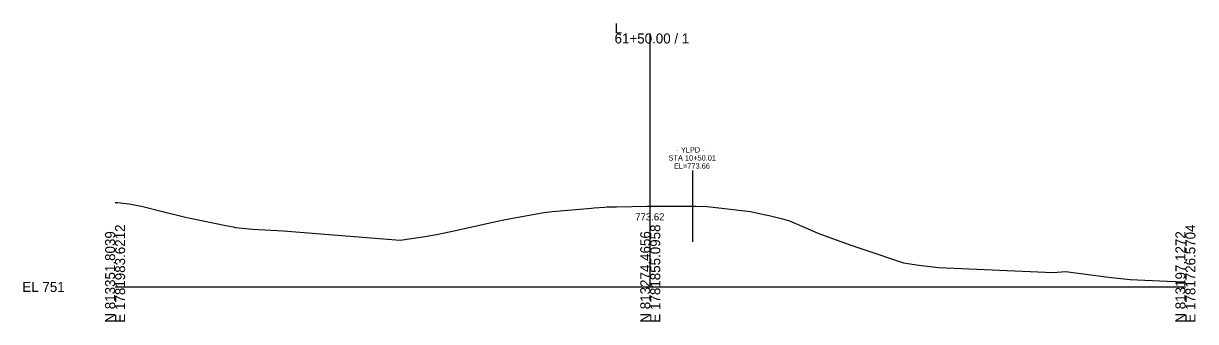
# Model space of a CAD drawing. Extents: x -26 to 7903, y -10 to 9573.
# Drawn here: x 2974.3 to 3302.8, y 2490.3 to 2573.8 of the extents above; entities that cross this region are included whole.
import ezdxf

# ---------------------------------------------------------------- set-up
doc = ezdxf.new("R2010")
doc.units = 0
for name, color, linetype in [('Exist Cross Section Cell', 7, 'Continuous'), ('Exist XS Center Line Elevation Label', 7, 'Continuous'), ('Exist XS Ground Line', 7, 'Continuous'), ('Prop XS Vertical Lines Alignments', 7, 'Continuous')]:
    doc.layers.add(name, color=color, linetype=linetype)

msp = doc.modelspace()

# ---------------------------------------------------------------- linework, layer by layer
at = {"layer": 'Exist Cross Section Cell'}
for p, q in [((3150, 2500), (3150, 2570.98)), ((3000, 2500), (3150, 2500)), ((3150, 2500), (3300, 2500))]:
    msp.add_line(p, q, dxfattribs=at)
at = {"layer": 'Exist XS Ground Line'}
for p, q in [((3000, 2523.66), (3000.63, 2523.6)), ((3000.63, 2523.6), (3003.95, 2523.3)), ((3003.95, 2523.3), (3007.73, 2522.55)), ((3007.73, 2522.55), (3012.95, 2521.25)), ((3012.95, 2521.25), (3019.36, 2519.66)), ((3110.92, 2519.14), (3120.14, 2520.81)), ((3120.14, 2520.81), (3122.53, 2521.09)), ((3122.53, 2521.09), (3133.51, 2522.1)), ((3133.51, 2522.1), (3134.3, 2522.16)), ((3134.3, 2522.16), (3137.18, 2522.36)), ((3137.18, 2522.36), (3137.89, 2522.41)), ((3137.89, 2522.41), (3140.53, 2522.46)), ((3140.53, 2522.46), (3149.16, 2522.61)), ((3149.16, 2522.61), (3150, 2522.62)), ((3150, 2522.62), (3161.26, 2522.64)), ((3161.26, 2522.64), (3162.76, 2522.61)), ((3162.76, 2522.61), (3165.81, 2522.53)), ((3165.81, 2522.53), (3166.77, 2522.41)), ((3166.77, 2522.41), (3178.06, 2521.16)), ((3178.06, 2521.16), (3181.79, 2520.3)), ((3181.79, 2520.3), (3183.35, 2519.96)), ((3183.35, 2519.96), (3187.05, 2519.07)), ((3019.36, 2519.66), (3021.02, 2519.26)), ((3021.02, 2519.26), (3031, 2517.24)), ((3031, 2517.24), (3033.08, 2516.87)), ((3033.08, 2516.87), (3033.78, 2516.68)), ((3033.78, 2516.68), (3038.47, 2516.18)), ((3094.09, 2515.49), (3107.16, 2518.38)), ((3107.16, 2518.38), (3108.99, 2518.81)), ((3108.99, 2518.81), (3110.92, 2519.14)), ((3187.05, 2519.07), (3188.99, 2518.52)), ((3188.99, 2518.52), (3193.75, 2516.44)), ((3038.47, 2516.18), (3047.14, 2515.71)), ((3047.14, 2515.71), (3079.89, 2513.13)), ((3079.89, 2513.13), (3086.23, 2514.03)), ((3086.23, 2514.03), (3090.04, 2514.65)), ((3090.04, 2514.65), (3094.09, 2515.49)), ((3193.75, 2516.44), (3195.09, 2515.85)), ((3195.09, 2515.85), (3196.93, 2515.09)), ((3196.93, 2515.09), (3206.5, 2511.62)), ((3206.5, 2511.62), (3212.62, 2509.53)), ((3212.62, 2509.53), (3218.13, 2507.7)), ((3218.13, 2507.7), (3220.96, 2506.71)), ((3220.96, 2506.71), (3225.27, 2506.05)), ((3225.27, 2506.05), (3230.82, 2505.47)), ((3230.82, 2505.47), (3262.92, 2504.05)), ((3262.92, 2504.05), (3266.37, 2504.29)), ((3266.37, 2504.29), (3278.48, 2502.7)), ((3278.48, 2502.7), (3284.5, 2502.07)), ((3284.5, 2502.07), (3294.85, 2501.64)), ((3294.85, 2501.64), (3300, 2501.44))]:
    msp.add_line(p, q, dxfattribs=at)
at = {"layer": 'Prop XS Vertical Lines Alignments'}
msp.add_line((3161.8, 2532.63), (3161.8, 2512.62), dxfattribs=at)

# ---------------------------------------------------------------- texts
at = {"layer": 'Exist Cross Section Cell'}
for s, p in [('L', (3140, 2570.98)), ('61+50.00 / 1', (3140, 2568.18)), ('EL 751', (2974, 2498.6))]:
    msp.add_text(s, height=2.8, dxfattribs=at).set_placement(p)
for s, p in [('E 1781983.6212', (3002.8, 2490)), ('E 1781855.0958', (3152.8, 2490)), ('E 1781726.5704', (3302.8, 2490)), ('N 813351.8039', (3000, 2490)), ('N 813274.4656', (3150, 2490)), ('N 813197.1272', (3300, 2490))]:
    msp.add_text(s, height=2.8, rotation=90, dxfattribs=at).set_placement(p)
at = {"layer": 'Exist XS Center Line Elevation Label'}
msp.add_text('773.62', height=2, dxfattribs=at).set_placement((3145.79, 2518.62))
at = {"layer": 'Prop XS Vertical Lines Alignments'}
for s, p in [('STA 10+50.01', (3155.12, 2535.38)), ('- YLPD -', (3157.31, 2537.63)), ('EL=773.66', (3156.63, 2533.13))]:
    msp.add_text(s, height=1.5, dxfattribs=at).set_placement(p)

doc.saveas('drawing.dxf')
